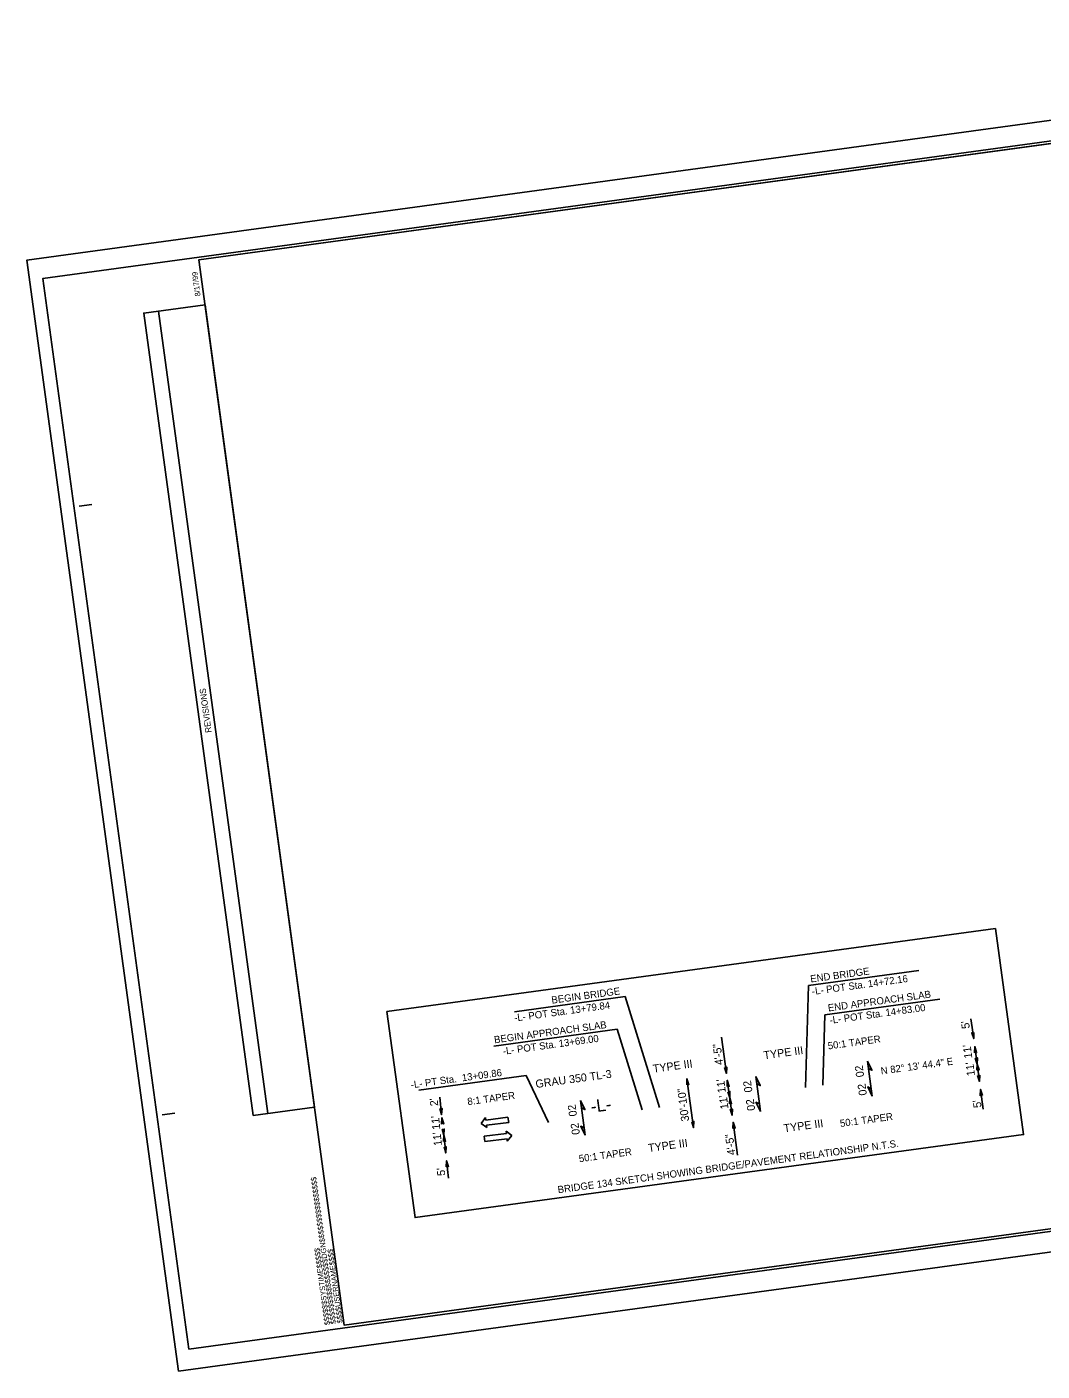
# Model space of a CAD drawing. Extents: x 2110836 to 2112652, y 581014 to 582326.
# Drawn here: x 2110836 to 2111828, y 581014 to 582326 of the extents above; entities that cross this region are included whole.
import ezdxf

# ---------------------------------------------------------------- set-up
doc = ezdxf.new("R2010")
doc.units = 0
for name, color, linetype in [('Prop DSN Text', 7, 'Continuous'), ('Prop Lane Arrow CELL', 7, 'Continuous'), ('Sheet Block Revision CELL', 7, 'Continuous'), ('Sheet Clip Boundary CELL', 7, 'Continuous'), ('Sheet Layout Plan Border', 7, 'Continuous'), ('Sheet Plan CELL', 7, 'Continuous'), ('Sheet Plot Border Inside CELL', 7, 'Continuous'), ('Sheet Plot Border Outside CELL', 7, 'Continuous')]:
    doc.layers.add(name, color=color, linetype=linetype)

msp = doc.modelspace()

# ---------------------------------------------------------------- linework, layer by layer
at = {"layer": 'Prop DSN Text'}
for p, q in [((2111599.7, 581390.2), (2111707.4, 581404.9)), ((2111599.7, 581390.2), (2111596.8, 581290.8)), ((2111420.5, 581379.4), (2111312.3, 581364.6)), ((2111420.5, 581379.4), (2111453.9, 581271.3)), ((2111615.6, 581361.6), (2111727.7, 581376.9)), ((2111615.6, 581361.6), (2111613.6, 581293.1)), ((2111758.2, 581357.9), (2111760.9, 581338.4)), ((2111412.8, 581347.6), (2111292.3, 581331.1)), ((2111412.8, 581347.6), (2111437.1, 581269)), ((2111514.6, 581339.8), (2111519.4, 581304.5)), ((2111761.9, 581330.6), (2111766.6, 581296.6)), ((2111657.2, 581316.3), (2111659.5, 581299.3)), ((2111219.1, 581288), (2111323.8, 581302.3)), ((2111345.6, 581256.5), (2111323.8, 581302.3)), ((2111548.1, 581301.5), (2111550.4, 581284.4)), ((2111480.8, 581299.2), (2111487.3, 581251.5)), ((2111520.3, 581297.7), (2111525, 581263.6)), ((2111659.5, 581299.3), (2111661.8, 581282.3)), ((2111767.6, 581288.8), (2111770.2, 581269.7)), ((2111239.5, 581281.3), (2111241.3, 581264.2)), ((2111376.8, 581278.1), (2111379.1, 581261.1)), ((2111550.4, 581284.4), (2111552.7, 581267.4)), ((2111379.1, 581261.1), (2111381.4, 581244)), ((2111525.9, 581256.8), (2111530.3, 581224.5)), ((2111243.5, 581244), (2111245.3, 581226.9)), ((2111246.2, 581219.1), (2111248, 581202.1))]:
    msp.add_line(p, q, dxfattribs=at)
for points in [[(2111187.9, 581364.8), (2111782.1, 581445.8), (2111809.6, 581244.8), (2111215.4, 581163.7)], [(2111761.1, 581344.5), (2111760.9, 581338.4), (2111759, 581344.2), (2111760.2, 581343.6)], [(2111761.7, 581324.6), (2111761.9, 581330.6), (2111763.8, 581324.8), (2111762.6, 581325.4)], [(2111657.2, 581316.3), (2111661.5, 581307.5), (2111658.1, 581309.2)], [(2111762.4, 581319.4), (2111764.2, 581313.6), (2111764.5, 581319.7), (2111763.5, 581318.8)], [(2111517.6, 581310.3), (2111519.4, 581304.5), (2111519.7, 581310.6), (2111518.7, 581309.7)], [(2111548.1, 581301.5), (2111552.4, 581292.6), (2111549, 581294.3)], [(2111764, 581307.5), (2111764.2, 581313.6), (2111766.1, 581307.8), (2111765, 581308.4)], [(2111764.7, 581302.4), (2111766.6, 581296.6), (2111766.8, 581302.7), (2111765.9, 581301.8)], [(2111480.6, 581293.2), (2111480.8, 581299.2), (2111482.7, 581293.4), (2111481.5, 581294)], [(2111520.1, 581291.6), (2111520.3, 581297.7), (2111522.2, 581291.8), (2111521.1, 581292.5)], [(2111661.8, 581282.3), (2111657.4, 581291.2), (2111660.8, 581289.4)], [(2111769.5, 581283), (2111767.6, 581288.8), (2111767.4, 581282.7), (2111768.3, 581283.6)], [(2111376.8, 581278.1), (2111381.2, 581269.2), (2111377.8, 581270.9)], [(2111520.8, 581286.5), (2111522.7, 581280.6), (2111522.9, 581286.8), (2111522, 581285.9)], [(2111522.5, 581274.6), (2111522.7, 581280.6), (2111524.5, 581274.8), (2111523.4, 581275.4)], [(2111552.7, 581267.4), (2111548.3, 581276.3), (2111551.7, 581274.6)], [(2111239.6, 581270.1), (2111241.3, 581264.2), (2111241.7, 581270.3), (2111240.7, 581269.4)], [(2111523.2, 581269.4), (2111525, 581263.6), (2111525.2, 581269.7), (2111524.3, 581268.8)], [(2111241.3, 581255), (2111241.6, 581261.1), (2111243.3, 581255.2), (2111242.2, 581255.9)], [(2111241.8, 581249.9), (2111243.5, 581244), (2111243.9, 581250.1), (2111242.9, 581249.2)], [(2111381.4, 581244), (2111377.1, 581252.9), (2111380.4, 581251.2)], [(2111485.5, 581257.3), (2111487.3, 581251.5), (2111487.6, 581257.6), (2111486.6, 581256.7)], [(2111525.7, 581250.7), (2111525.9, 581256.8), (2111527.8, 581250.9), (2111526.6, 581251.6)], [(2111243.1, 581237.9), (2111243.5, 581244), (2111245.2, 581238.1), (2111244, 581238.8)], [(2111243.7, 581232.8), (2111245.3, 581226.9), (2111245.7, 581233), (2111244.8, 581232.2)], [(2111245.8, 581213.1), (2111246.2, 581219.1), (2111247.9, 581213.3), (2111246.7, 581213.9)]]:
    msp.add_lwpolyline(points, close=True, dxfattribs=at)
at = {"layer": 'Prop Lane Arrow CELL'}
for p, q in [((2111279.9, 581255.7), (2111284.2, 581261.3)), ((2111285.3, 581251.5), (2111279.9, 581255.7)), ((2111284.2, 581261.3), (2111284.4, 581258.9)), ((2111284.4, 581258.9), (2111306.1, 581261.6)), ((2111306.8, 581256.4), (2111285, 581253.8)), ((2111285, 581253.8), (2111285.3, 581251.5)), ((2111306.1, 581261.6), (2111306.8, 581256.4)), ((2111282.8, 581243.1), (2111304.5, 581245.7)), ((2111283.4, 581238), (2111282.8, 581243.1)), ((2111305.2, 581240.6), (2111283.4, 581238)), ((2111304.5, 581245.7), (2111304.3, 581248)), ((2111304.3, 581248), (2111309.7, 581243.8)), ((2111305.4, 581238.3), (2111305.2, 581240.6)), ((2111309.7, 581243.8), (2111305.4, 581238.3))]:
    msp.add_line(p, q, dxfattribs=at)
at = {"layer": 'Sheet Block Revision CELL'}
msp.add_line((2111071.6, 581265.4), (2110964.7, 582048.8), dxfattribs=at)
msp.add_lwpolyline([(2111057.2, 581263.4), (2110950.3, 582046.8), (2111010.2, 582055), (2111117.1, 581271.6)], close=True, dxfattribs=at)
at = {"layer": 'Sheet Clip Boundary CELL'}
msp.add_lwpolyline([(2111146.2, 581058.6), (2112632.4, 581261.4), (2112519.1, 582092.2), (2112282, 582059.9), (2112253.4, 582269.4), (2111004.2, 582098.9)], close=True, dxfattribs=at)
at = {"layer": 'Sheet Layout Plan Border'}
msp.add_lwpolyline([(2111146.2, 581058.6), (2112632.5, 581261.4), (2112519.1, 582092.2), (2112282, 582059.9), (2112253.4, 582269.4), (2111004.2, 582098.9)], close=True, dxfattribs=at)
at = {"layer": 'Sheet Plan CELL'}
for p, q in [((2111004.2, 582098.9), (2111004.2, 582098.9)), ((2110887.2, 581858.4), (2110899.6, 581860.1)), ((2110968.3, 581263.9), (2110980.7, 581265.6)), ((2111146.2, 581058.6), (2111146.2, 581058.6))]:
    msp.add_line(p, q, dxfattribs=at)
for points in [[(2112490.5, 582301.8), (2111004.2, 582098.9), (2111146.2, 581058.6), (2112632.4, 581261.4)], [(2111146.2, 581058.6), (2111004.2, 582098.9), (2112292.2, 582274.7), (2112312.5, 582126), (2112510.7, 582153.1), (2112632.4, 581261.4)]]:
    msp.add_lwpolyline(points, close=True, dxfattribs=at)
at = {"layer": 'Sheet Plot Border Inside CELL'}
msp.add_lwpolyline([(2110994.5, 581035.3), (2112645.1, 581260.6), (2112502.5, 582305.9), (2110851.8, 582080.6)], close=True, dxfattribs=at)
at = {"layer": 'Sheet Plot Border Outside CELL'}
msp.add_lwpolyline([(2110984.3, 581013.8), (2112652.3, 581241.4), (2112504.3, 582326.3), (2110836.2, 582098.7)], close=True, dxfattribs=at)

# ---------------------------------------------------------------- texts
at = {"layer": 'Prop DSN Text'}
for s, height, rotation, p in [('END BRIDGE', 7, 7.771, (2111601.8, 581393.2)), ('-L- POT Sta. 14+72.16', 7, 7.771, (2111603.4, 581381)), ('BEGIN BRIDGE', 7, 7.771, (2111349, 581372.5)), ('END APPROACH SLAB', 7, 7.771, (2111619, 581364.9)), ('-L- POT Sta. 13+79.84  ', 7, 7.771, (2111312.6, 581355.1)), ('-L- POT Sta. 14+83.00', 7, 7.771, (2111620.6, 581352.8)), ('BEGIN APPROACH SLAB', 7, 7.771, (2111293, 581333.8)), ("5'", 7.81, 98.441, (2111757.2, 581348.6)), ('-L- POT Sta. 13+69.00', 7, 7.771, (2111301.5, 581322.6)), ('50:1 TAPER', 7, 7.771, (2111618.9, 581327.8)), ('4\'-5"', 7.81, 97.101, (2111516.3, 581313.1)), ('TYPE III', 7.81, 7.771, (2111556.3, 581318.2)), ("11'", 7.81, 97.101, (2111759.6, 581319.5)), ('TYPE III', 7.81, 7.771, (2111448.2, 581305.1)), ('N 82%%d 13\' 44.4" E', 7, 7.771, (2111670.6, 581303.4)), ("11'", 7.81, 97.101, (2111762.2, 581302.4)), (' -L- PT Sta.  13+09.86', 7, 7.771, (2111209, 581289.5)), ('GRAU 350 TL-3', 7.812, 7.771, (2111333.5, 581290.2)), ('02', 7.81, 97.7876, (2111654, 581301.3)), ('30\'-10"', 7.81, 97.101, (2111483.1, 581258)), ("11'", 7.81, 97.101, (2111518.9, 581285.9)), ('02', 7.81, 97.7876, (2111544.9, 581286.4)), ('02', 7.81, 97.7876, (2111656.7, 581283.4)), ("2'", 7.81, 95.4906, (2111238, 581272.9)), ('8:1 TAPER', 7, 7.771, (2111266.9, 581273.4)), ('-L-', 12.3, 7.771, (2111387.8, 581266)), ("11'", 7.81, 97.101, (2111521.5, 581270)), ('02', 7.81, 97.7876, (2111547.6, 581268.5)), ("5'", 7.81, 98.441, (2111768.7, 581271.4)), ("11'", 7.81, 95.4906, (2111240, 581249.9)), ('02', 7.81, 97.7876, (2111373.6, 581263)), ('50:1 TAPER', 7, 7.771, (2111630.8, 581252.1)), ('02', 7.81, 97.7876, (2111376.4, 581245.1)), ('TYPE III', 7.81, 7.771, (2111575.9, 581246.9)), ("11'", 7.81, 95.4906, (2111241.6, 581234)), ('BRIDGE 134 SKETCH SHOWING BRIDGE/PAVEMENT RELATIONSHIP N.T.S.', 7, 7.771, (2111355.1, 581187.4)), ('TYPE III', 7.81, 7.771, (2111443.5, 581227.7)), ('4\'-5"', 7.81, 97.101, (2111528.3, 581225.1)), ('50:1 TAPER', 7, 7.771, (2111375.8, 581217.7)), ("5'", 7.81, 95.4906, (2111244.9, 581204.8))]:
    msp.add_text(s, height=height, rotation=rotation, dxfattribs=at).set_placement(p)
at = {"layer": 'Sheet Block Revision CELL'}
msp.add_text('REVISIONS', height=6, rotation=97.771, dxfattribs=at).set_placement((2111016.7, 581637.5))
at = {"layer": 'Sheet Plan CELL'}
for s, p in [('8/17/99', (2111005.8, 582063.6)), ('$$$$$$$$$$$$$$$$DGN$$$$$$$$$$$$$$$$', (2111138.3, 581059.9)), ('$$$$$$SYSTIME$$$$$', (2111132.3, 581059)), ('$$$$USERNAME$$$$', (2111144.8, 581060.8))]:
    msp.add_text(s, height=5.25, rotation=97.771, dxfattribs=at).set_placement(p)

doc.saveas('drawing.dxf')
